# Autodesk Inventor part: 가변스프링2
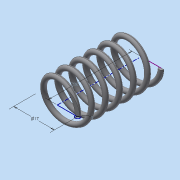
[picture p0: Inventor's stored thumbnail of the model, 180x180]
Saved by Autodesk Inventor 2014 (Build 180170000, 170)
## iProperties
Created: 2023-01
Part Number: 가변스프링2
Material: 일반
Document SubType Name: Modeling
Designer: dg
Density: 1 g/cm^3
Appearance: 기본값
Author: dg
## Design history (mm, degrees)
sketch "스케치1"
  geometry: L1 (8.5, 0)-(0, 0); L2 (0, 0)-(0, 35); L3 (0, 35)-(8.5, 35); C1 r 1 at (8.5, 0)
  constraints: 6 end point, 1 centre point, 1 coincident, 1 horizontal, 1 parallel, 1 perpendicular, 1 vertical alignment
  dimensions: "d0" = 17 diameter of L1.start L2; "d1" = 35 distance of L1.end L2.end (derived); "d2" = 2 diameter of C1
feature "코일1" pitch "d3" = 10; turns "d5" = 6; dims "d4" = 35 (= d1), "d6" = 0, angle "d7" = 90 deg, angle "d8" = 90 deg, "d9" = 0, "d10" = 0
node "작업 평면1"
node "작업 평면2"
feature "분할1"
feature "분할2"
node "솔리드1"
other parameters: "d11" = 90 deg, "d12" = 90 deg
